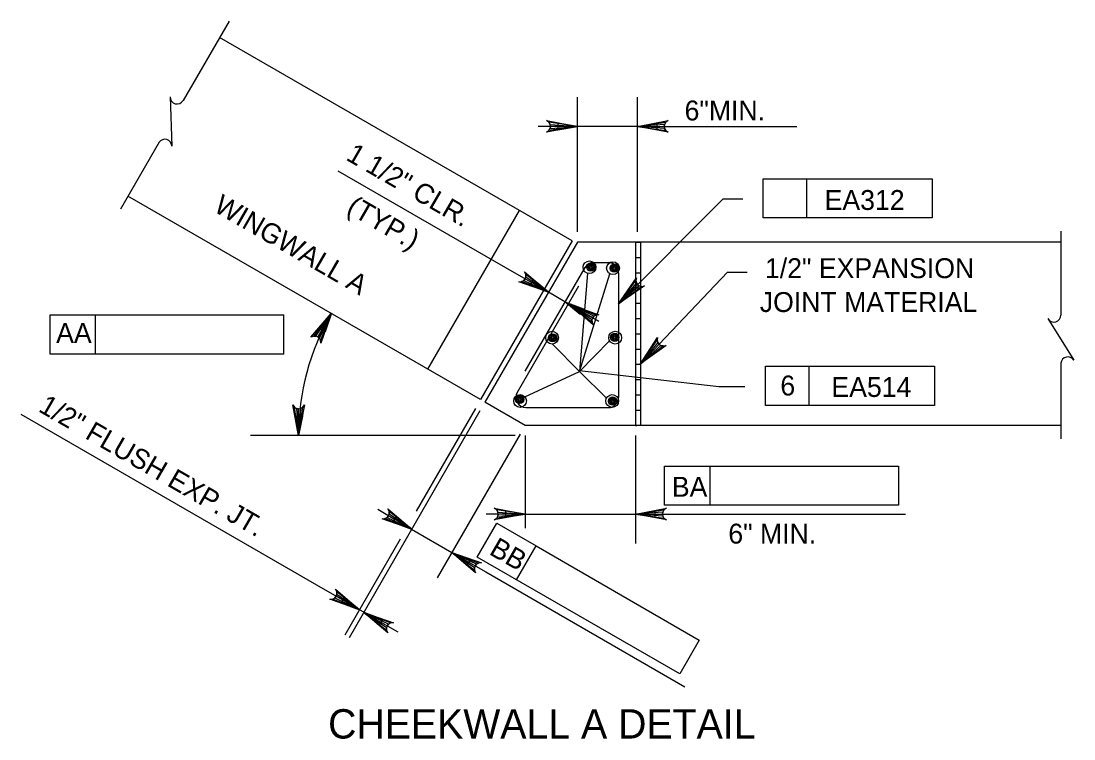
# Model space of a CAD drawing. Extents: x 638255 to 640306, y 296059 to 298435.
# Drawn here: x 638543 to 638701.7, y 297517 to 297625.2 of the extents above; entities that cross this region are included whole.
import ezdxf

# ---------------------------------------------------------------- set-up
doc = ezdxf.new("R2010")
doc.units = 0
for name, color, linetype in [('Level 10', 7, 'Continuous'), ('Level 3', 7, 'Continuous'), ('Level 4', 7, 'Continuous'), ('Level 5', 7, 'Continuous')]:
    doc.layers.add(name, color=color, linetype=linetype)

msp = doc.modelspace()

# ---------------------------------------------------------------- linework, layer by layer
at = {"layer": 'Level 10'}
for p, q in [((638626.08, 297592.1), (638572.96, 297622.78)), ((638612.27, 297568.17), (638559.14, 297598.85)), ((638618.11, 297596.71), (638604.29, 297572.78)), ((638626.08, 297592.1), (638612.27, 297568.17)), ((638626.86, 297591.92), (638612.93, 297567.79)), ((638699.72, 297591.92), (638626.86, 297591.92)), ((638635.62, 297591.92), (638635.62, 297564.29)), ((638636.38, 297591.92), (638636.38, 297564.29)), ((638619, 297564.29), (638612.93, 297567.79)), ((638699.72, 297564.29), (638619, 297564.29))]:
    msp.add_line(p, q, dxfattribs=at)
at = {"layer": 'Level 3'}
for p, q in [((638626.86, 297593.45), (638626.86, 297613.77)), ((638635.9, 297593.45), (638635.9, 297613.77)), ((638626.86, 297609.36), (638620.97, 297609.36)), ((638635.9, 297609.36), (638626.86, 297609.36)), ((638635.9, 297609.36), (638659.92, 297609.36)), ((638617.4, 297587.31), (638590.84, 297602.64)), ((638654.85, 297601.47), (638680.34, 297601.47)), ((638654.85, 297595.58), (638654.85, 297601.47)), ((638661.43, 297595.58), (638661.43, 297601.47)), ((638680.34, 297601.47), (638680.34, 297595.58)), ((638633.08, 297582.64), (638648.83, 297598.42)), ((638648.83, 297598.42), (638651.78, 297598.42)), ((638680.34, 297595.58), (638654.85, 297595.58)), ((638622.5, 297584.36), (638617.4, 297587.31)), ((638636.38, 297573.58), (638649.49, 297587.37)), ((638649.49, 297587.37), (638652.44, 297587.37)), ((638622.26, 297583.94), (638620.29, 297580.53)), ((638547.43, 297580.94), (638554.26, 297580.94)), ((638547.43, 297575.04), (638547.43, 297580.94)), ((638554.26, 297575.04), (638554.26, 297580.94)), ((638554.26, 297580.94), (638582.66, 297580.94)), ((638582.66, 297575.04), (638582.66, 297580.94)), ((638582.66, 297575.04), (638547.43, 297575.04)), ((638655.19, 297573.21), (638680.68, 297573.21)), ((638655.19, 297567.31), (638655.19, 297573.21)), ((638661.77, 297567.31), (638661.77, 297573.21)), ((638680.68, 297573.21), (638680.68, 297567.31)), ((638648.18, 297570.15), (638652.12, 297570.15)), ((638680.68, 297567.31), (638655.19, 297567.31)), ((638588.93, 297539.44), (638543.05, 297565.93)), ((638612.17, 297566.46), (638592.49, 297532.28)), ((638611.5, 297566.84), (638602.59, 297551.36)), ((638617.47, 297562.75), (638577.64, 297562.75)), ((638618.23, 297562.96), (638605.74, 297541.32)), ((638619, 297562.75), (638619, 297548.8)), ((638635.62, 297562.75), (638635.62, 297546.5)), ((638640.01, 297552.25), (638640.01, 297558.14)), ((638640.01, 297558.14), (638646.85, 297558.14)), ((638646.85, 297552.25), (638646.85, 297558.14)), ((638646.85, 297558.14), (638675.25, 297558.14)), ((638675.25, 297558.14), (638675.25, 297552.25)), ((638599.33, 297550.12), (638596.78, 297551.59)), ((638675.25, 297552.25), (638640.01, 297552.25)), ((638611.78, 297544.43), (638614.73, 297549.53)), ((638616.06, 297550.92), (638613.11, 297550.92)), ((638614.73, 297549.53), (638620.65, 297546.11)), ((638619, 297550.92), (638643.31, 297550.92)), ((638638.56, 297550.92), (638641.51, 297550.92)), ((638641.51, 297550.92), (638676.3, 297550.92)), ((638601.88, 297548.65), (638607.95, 297545.14)), ((638600.17, 297547.15), (638591.82, 297532.66)), ((638617.7, 297541.01), (638620.65, 297546.11)), ((638620.65, 297546.11), (638645.24, 297531.91)), ((638610.5, 297543.67), (638613.05, 297542.2)), ((638642.3, 297526.81), (638611.78, 297544.43)), ((638613.05, 297542.2), (638643.05, 297524.88)), ((638591.48, 297537.97), (638588.93, 297539.44)), ((638594.7, 297536.11), (638594.03, 297536.49)), ((638597.25, 297534.63), (638599.8, 297533.16)), ((638645.24, 297531.91), (638642.3, 297526.81))]:
    msp.add_line(p, q, dxfattribs=at)
for points in [[(638626.86, 297609.36), (638622.21, 297608.48), (638622.57, 297608.73), (638622.75, 297609.04), (638622.81, 297609.36), (638622.75, 297609.67), (638622.57, 297609.98), (638622.21, 297610.23), (638626.86, 297609.36), (638622.57, 297609.98), (638622.75, 297609.67), (638626.86, 297609.36), (638622.81, 297609.36), (638622.75, 297609.04), (638626.86, 297609.36), (638622.57, 297608.73)], [(638635.9, 297609.36), (638640.56, 297610.23), (638640.2, 297609.98), (638640.01, 297609.67), (638639.96, 297609.36), (638640.01, 297609.04), (638640.2, 297608.73), (638640.56, 297608.48), (638635.9, 297609.36), (638640.2, 297608.73), (638640.01, 297609.04), (638635.9, 297609.36), (638639.96, 297609.36), (638640.01, 297609.67), (638635.9, 297609.36), (638640.2, 297609.98)], [(638622.5, 297584.36), (638618.03, 297585.93), (638618.47, 297585.97), (638618.79, 297586.15), (638618.99, 297586.39), (638619.1, 297586.69), (638619.1, 297587.05), (638618.91, 297587.44), (638622.5, 297584.36), (638619.1, 297587.05), (638619.1, 297586.69), (638622.5, 297584.36), (638618.99, 297586.39), (638618.79, 297586.15), (638622.5, 297584.36), (638618.47, 297585.97)], [(638633.08, 297582.64), (638635.75, 297586.55), (638635.67, 297586.12), (638635.76, 297585.77), (638635.94, 297585.51), (638636.2, 297585.33), (638636.55, 297585.24), (638636.98, 297585.32), (638633.08, 297582.64), (638636.55, 297585.24), (638636.2, 297585.33), (638633.08, 297582.64), (638635.94, 297585.51), (638635.76, 297585.77), (638633.08, 297582.64), (638635.67, 297586.12)], [(638589.77, 297581.16), (638588.21, 297576.7), (638588.17, 297577.13), (638587.99, 297577.45), (638587.75, 297577.65), (638587.45, 297577.76), (638587.09, 297577.75), (638586.69, 297577.57), (638589.77, 297581.16), (638587.09, 297577.75), (638587.45, 297577.76), (638589.77, 297581.16), (638587.75, 297577.65), (638587.99, 297577.45), (638589.77, 297581.16), (638588.17, 297577.13)], [(638636.38, 297573.58), (638638.96, 297577.56), (638638.89, 297577.13), (638638.99, 297576.78), (638639.18, 297576.52), (638639.44, 297576.35), (638639.79, 297576.27), (638640.22, 297576.35), (638636.38, 297573.58), (638639.79, 297576.27), (638639.44, 297576.35), (638636.38, 297573.58), (638639.18, 297576.52), (638638.99, 297576.78), (638636.38, 297573.58), (638638.89, 297577.13)], [(638584.85, 297562.75), (638583.98, 297567.4), (638584.23, 297567.05), (638584.54, 297566.86), (638584.85, 297566.81), (638585.17, 297566.86), (638585.48, 297567.05), (638585.73, 297567.4), (638584.85, 297562.75), (638585.48, 297567.05), (638585.17, 297566.86), (638584.85, 297562.75), (638584.85, 297566.81), (638584.54, 297566.86), (638584.85, 297562.75), (638584.23, 297567.05)], [(638601.9, 297548.63), (638597.44, 297550.21), (638597.87, 297550.24), (638598.19, 297550.42), (638598.39, 297550.66), (638598.5, 297550.96), (638598.5, 297551.32), (638598.31, 297551.72), (638601.9, 297548.63), (638598.5, 297551.32), (638598.5, 297550.96), (638601.9, 297548.63), (638598.39, 297550.66), (638598.19, 297550.42), (638601.9, 297548.63), (638597.87, 297550.24)], [(638619, 297550.92), (638614.35, 297550.05), (638614.71, 297550.29), (638614.89, 297550.61), (638614.95, 297550.92), (638614.89, 297551.23), (638614.71, 297551.54), (638614.35, 297551.79), (638619, 297550.92), (638614.71, 297551.54), (638614.89, 297551.23), (638619, 297550.92), (638614.95, 297550.92), (638614.89, 297550.61), (638619, 297550.92), (638614.71, 297550.29)], [(638635.62, 297550.92), (638640.27, 297551.79), (638639.91, 297551.54), (638639.72, 297551.23), (638639.67, 297550.92), (638639.72, 297550.61), (638639.91, 297550.29), (638640.27, 297550.05), (638635.62, 297550.92), (638639.91, 297550.29), (638639.72, 297550.61), (638635.62, 297550.92), (638639.67, 297550.92), (638639.72, 297551.23), (638635.62, 297550.92), (638639.91, 297551.54)], [(638607.95, 297545.14), (638612.41, 297543.58), (638611.98, 297543.54), (638611.66, 297543.36), (638611.46, 297543.12), (638611.35, 297542.82), (638611.36, 297542.46), (638611.54, 297542.06), (638607.95, 297545.14), (638611.36, 297542.46), (638611.35, 297542.82), (638607.95, 297545.14), (638611.46, 297543.12), (638611.66, 297543.36), (638607.95, 297545.14), (638611.98, 297543.54)], [(638594.03, 297536.5), (638589.56, 297538.07), (638590, 297538.1), (638590.31, 297538.28), (638590.52, 297538.52), (638590.62, 297538.82), (638590.62, 297539.18), (638590.44, 297539.58), (638594.03, 297536.5), (638590.62, 297539.18), (638590.62, 297538.82), (638594.03, 297536.5), (638590.52, 297538.52), (638590.31, 297538.28), (638594.03, 297536.5), (638590, 297538.1)], [(638594.71, 297536.1), (638599.17, 297534.53), (638598.74, 297534.5), (638598.42, 297534.32), (638598.22, 297534.08), (638598.11, 297533.78), (638598.11, 297533.42), (638598.3, 297533.02), (638594.71, 297536.1), (638598.11, 297533.42), (638598.11, 297533.78), (638594.71, 297536.1), (638598.22, 297534.08), (638598.42, 297534.32), (638594.71, 297536.1), (638598.74, 297534.5)]]:
    msp.add_lwpolyline(points, dxfattribs=at)
for points in [[(638623.92, 297609.85), (638623.92, 297608.87), (638626.86, 297609.36)], [(638638.85, 297609.85), (638638.85, 297608.87), (638635.9, 297609.36)], [(638620.2, 297586.26), (638619.7, 297585.41), (638622.5, 297584.36)], [(638588.87, 297578.39), (638588, 297578.84), (638589.8, 297581.22)], [(638584.48, 297565.72), (638585.46, 297565.68), (638584.85, 297562.75)], [(638616.06, 297551.41), (638616.06, 297550.43), (638619, 297550.92)], [(638638.56, 297551.41), (638638.56, 297550.43), (638635.62, 297550.92)], [(638599.57, 297550.55), (638599.08, 297549.7), (638601.88, 297548.65)], [(638610.74, 297544.1), (638610.25, 297543.24), (638607.95, 297545.14)], [(638591.73, 297538.39), (638591.24, 297537.54), (638594.03, 297536.49)], [(638597.49, 297535.06), (638597, 297534.21), (638594.7, 297536.11)]]:
    msp.add_lwpolyline(points, close=True, dxfattribs=at)
msp.add_arc((638621.79, 297562.75), 36.94, 150.1038, 180, dxfattribs=at)
at = {"layer": 'Level 4'}
for p, q in [((638574.38, 297625.25), (638567.47, 297613.28)), ((638565.49, 297613.81), (638565.77, 297606.4)), ((638563.84, 297606.98), (638558.01, 297596.88)), ((638699.72, 297593.56), (638699.72, 297582.31)), ((638699.72, 297582.31), (638699.72, 297580.93)), ((638697.74, 297580.4), (638701.68, 297574.13)), ((638699.72, 297573.66), (638699.72, 297572.43)), ((638699.72, 297572.43), (638699.72, 297562.27))]:
    msp.add_line(p, q, dxfattribs=at)
for centre, start, end in [((638566.55, 297613.81), 180, 330), ((638564.71, 297606.36), 2.1328, 144.6714), ((638698.66, 297580.93), 210, 0), ((638700.78, 297573.56), 32.1328, 174.6714)]:
    msp.add_arc(centre, 1.06, start, end, dxfattribs=at)
at = {"layer": 'Level 5'}
for p, q in [((638635.62, 297591.92), (638636.38, 297591.92)), ((638635.62, 297589.61), (638636.38, 297589.61)), ((638627.97, 297588.07), (638618.97, 297572.48)), ((638629.3, 297588.84), (638631.54, 297588.84)), ((638628.38, 297587.22), (638627.2, 297572.39)), ((638627.2, 297572.39), (638631.76, 297587.15)), ((638633.08, 297587.31), (638633.08, 297568.5)), ((638635.62, 297587.31), (638636.38, 297587.31)), ((638627.03, 297585.3), (638617.78, 297569.27)), ((638635.62, 297585.01), (638636.38, 297585.01)), ((638624.99, 297582.92), (638622.5, 297584.36)), ((638625.66, 297582.54), (638630.1, 297579.98)), ((638635.62, 297582.71), (638636.38, 297582.71)), ((638635.62, 297580.41), (638636.38, 297580.41)), ((638635.62, 297578.1), (638636.38, 297578.1)), ((638623.11, 297576.55), (638627.2, 297572.39)), ((638627.2, 297572.39), (638631.72, 297577.04)), ((638635.62, 297575.8), (638636.38, 297575.8)), ((638635.61, 297573.5), (638636.38, 297573.5)), ((638618.97, 297568.6), (638627.2, 297572.39)), ((638627.2, 297572.56), (638648.18, 297570.15)), ((638627.2, 297572.39), (638631.25, 297568.41)), ((638635.62, 297571.2), (638636.38, 297571.2)), ((638635.61, 297568.89), (638636.38, 297568.89)), ((638619.11, 297566.97), (638631.54, 297566.97)), ((638635.62, 297566.59), (638636.38, 297566.59)), ((638635.61, 297564.29), (638635.83, 297564.29))]:
    msp.add_line(p, q, dxfattribs=at)
msp.add_lwpolyline([(638627.79, 297581.88), (638627.3, 297581.02), (638624.99, 297582.92)], close=True, dxfattribs=at)
msp.add_lwpolyline([(638625.66, 297582.54), (638630.12, 297580.97), (638629.69, 297580.93), (638629.37, 297580.75), (638629.17, 297580.51), (638629.06, 297580.21), (638629.07, 297579.85), (638629.25, 297579.46), (638625.66, 297582.54), (638629.07, 297579.85), (638629.06, 297580.21), (638625.66, 297582.54), (638629.17, 297580.51), (638629.37, 297580.75), (638625.66, 297582.54), (638629.69, 297580.93)], dxfattribs=at)
for centre, radius in [((638628.69, 297588.13), 0.96), ((638628.9, 297588.15), 0.624), ((638628.9, 297588.15), 0.468), ((638628.9, 297588.15), 0.312), ((638628.9, 297588.15), 0.156), ((638632.23, 297587.99), 0.96), ((638632.43, 297588), 0.624), ((638632.43, 297588), 0.468), ((638632.43, 297588), 0.312), ((638632.43, 297588), 0.156), ((638623.05, 297577.51), 0.96), ((638623.14, 297577.49), 0.624), ((638632.56, 297577.51), 0.96), ((638632.5, 297577.56), 0.624), ((638632.5, 297577.56), 0.468), ((638623.14, 297577.49), 0.468), ((638623.14, 297577.49), 0.312), ((638623.14, 297577.49), 0.156), ((638632.5, 297577.56), 0.312), ((638632.5, 297577.56), 0.156), ((638618.24, 297567.97), 0.96), ((638618.18, 297568.19), 0.624), ((638618.18, 297568.19), 0.468), ((638632.11, 297567.97), 0.96), ((638632.19, 297567.95), 0.624), ((638618.18, 297568.19), 0.312), ((638618.18, 297568.19), 0.156), ((638632.19, 297567.95), 0.468), ((638632.19, 297567.95), 0.312), ((638632.19, 297567.95), 0.156)]:
    msp.add_circle(centre, radius, dxfattribs=at)
for centre, start, end in [((638629.3, 297587.3), 90, 150), ((638631.55, 297587.3), 0, 90), ((638619.11, 297568.5), 150, 270), ((638631.55, 297568.5), 270, 0)]:
    msp.add_arc(centre, 1.53, start, end, dxfattribs=at)

# ---------------------------------------------------------------- texts
at = {"layer": 'Level 3'}
for s, height, p in [('6"MIN.', 3, (638643.02, 297610.26)), ('EA312', 3, (638664.12, 297596.77)), ('1/2" EXPANSION', 3.0001, (638655.13, 297586.49)), ('JOINT MATERIAL', 3.0001, (638654.35, 297581.38)), ('AA', 3, (638548.34, 297576.72)), ('6', 3, (638657.45, 297568.8)), ('EA514', 3, (638665.14, 297568.58)), ('BA', 3, (638641.1, 297553.53)), ('6" MIN.', 3, (638649.61, 297546.47)), ('CHEEKWALL A DETAIL', 4.4207, (638589.31, 297517.08))]:
    msp.add_text(s, height=height, dxfattribs=at).set_placement(p)
for s, height, p in [('1 1/2" CLR.', 3.0001, (638591.85, 297604.4)), ('WINGWALL A', 3, (638571.89, 297596.65)), ('(TYP.)', 3, (638591.91, 297596.46)), ('1/2" FLUSH EXP. JT.', 3.0001, (638545.51, 297566.48)), ('BB', 3, (638613.42, 297544.94))]:
    msp.add_text(s, height=height, rotation=330, dxfattribs=at).set_placement(p)

doc.saveas('drawing.dxf')
